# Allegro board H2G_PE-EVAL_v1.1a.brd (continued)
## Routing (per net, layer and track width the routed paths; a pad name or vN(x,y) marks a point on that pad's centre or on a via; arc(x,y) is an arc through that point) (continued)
N08455: length 2.8
  TOP w0.254: R11.2 85.78,77.09 85,77.86 U3.11
N08467: length 6
  TOP w0.254: R11.1 93.1,77.09 93.24,76.95 C20.2
N09759: length 33
  TOP w0.254: R14.2 67.06,74.82 68.19,75.95 72.14,75.95 v1(74.42,73.66) ; U3.7 80.92,77.36 v1(81.53,77.98)
  TOP w0.635: R14.2 65.53,74.42 63.43,76.52 63.43,78.67 63.88,79.12 Q3.3 Q3.1
  BOTTOM w0.254: v1(74.42,73.66) 80.01,73.66 81.53,75.18 v1(81.53,77.98)
N09873: length 35.9
  TOP w0.254: Q3.8 71.43,81.66 73.08,83.31 80.52,83.31 82.04,81.79 R12.2
  TOP w0.635: Q3.6 70.49,80.39 ; Q3.6 68.55,79.12 Q3.9 68.55,80.39 70.49,80.39 ; Q3.6 Q3.5 ; 70.49,80.39 Q3.8 70.49,87.73 69.56,88.66 TX1.4
N10901: length 17.3
  TOP w0.254: U3.6 79.06,77.86 78.74,77.54 v1(78.74,75.95) ; v1(73.91,75.95) 73.15,76.71 65.68,76.71 65.15,77.24 Q3.4
  BOTTOM w0.254: v1(78.74,75.95) v1(73.91,75.95)
N10913: length 5.2
  TOP w0.254: R12.1 88.15,81.03 87.9,80.77 85.34,80.77 84.94,80.36 U3.16
N10917: length 2.7
  TOP w0.254: R13.1 85.26,79.88 84.74,79.36 U3.14
N11491: length 3
  TOP w0.635: TX1.12 81.66,94.66 D7.2
N11495: length 2.8
  TOP w0.635: TX1.11 82.08,92.66 D6.2
N11499: length 2.7
  TOP w0.635: TX1.10 82.36,90.66 D5.2
N11507: length 2.6
  TOP w0.635: D8.2 65.78,84.66 TX1.6
N11532: length 2.5
  TOP w0.635: TX1.5 65.5,86.66 D9.2
N38522: length 2.4
  TOP w0.635: R15.2 D17.2
N38634: length 3.2
  TOP w0.635: R16.2 D18.2
N41110: length 4.8
  TOP w0.381: U6.6 84.3,15.37 84.59,15.67 C50.1
N41352: length 3.8
  TOP w0.381: U7.6 59.73,15.37 60.46,16.11 C51.1
N48243: length 24.5
  TOP w0.254: v1(14.99,67.56) 14.38,67.56 14.27,67.45 U16.3 ; C62.2 v1(24.47,79.63) 24.47,81.25 24.64,81.42 ; R35.2 24.64,81.42 24.64,81.42 ; 24.64,81.42 24.64,81.15 24.89,80.9 R37.2
  LAYER3 w0.254: v1(24.47,79.63) 20.55,75.71 17.54,75.71 16.11,74.28 16.11,68.69 v1(14.99,67.56)
N48256: length 3.1
  TOP w0.254: U20.7 28.92,80.9 27.65,82.17 R35.1
N48260: length 3.1
  TOP w0.254: R36.1 27.65,83.44 28.92,82.17 U20.6
N48264: length 31.1
  TOP w0.254: 13.96,82.19 14.1,82.19 C61.1 ; 13.96,82.19 11.43,79.66 11.43,68.58 11.91,68.1 U16.2 ; 13.96,82.19 13.96,83.36 ; R38.1 14.14,83.36 13.96,83.36 ; 13.96,83.36 15.17,84.58 24.68,84.58 25.39,83.87 R36.2
N48807: length 16.8
  TOP w0.254: 42.93,80.9 50.67,80.9 52.32,82.55 R33.2 ; 42.93,80.9 U20.2 ; 42.93,80.9 43.02,80.99 R39.1 43.04,82.44 C58.1
N51115: length 28.2
  TOP w0.254: R43.2 23.37,75.18 23.11,74.93 23.11,72.39 ; 23.11,72.39 23.11,72.39 23.11,71.42 ; 23.11,72.39 R41.2 ; U16.5 14.48,66.15 14.91,65.72 v1(14.91,64.85) ; 23.11,71.42 22.8,71.12 21.08,71.12 v1(20.32,71.88) ; 23.11,71.42 23.67,70.87 C67.2
  LAYER3 w0.254: v1(20.32,71.88) 19.3,70.87 19.3,66.04 18.11,64.85 v1(14.91,64.85)
N51119: length 2.4
  TOP w0.254: 29.43,72.52 28.17,72.52 28.04,72.39 R41.1
N51123: length 2.4
  TOP w0.254: R42.1 U21.6
N51127: length 41.1
  TOP w0.254: U16.6 10.7,65.5 10.17,66.03 v1(10.17,75.95) ; C66.1 R44.1 14.21,80.76 14.73,81.28 17.02,81.28 17.4,80.9 v1(17.4,74.27) ; R42.2 24.5,73.79 v1(24.14,74.14)
  LAYER3 w0.254: v1(24.14,74.14) 23.36,74.14 23.23,74.27 v1(17.4,74.27)
  BOTTOM w0.254: v1(17.4,74.27) 16.48,75.18 10.93,75.18 v1(10.17,75.95)
N51293: length 160.9
  TOP w0.254: R40.2 117.6,8.13 115.57,6.1 v1(115.57,2.29) ; C63.1 R45.1 45.97,73.91 46.99,72.9 v1(46.99,70.61) 42.42,70.61 41.66,71.37 41.66,72.29 41.43,72.52 40.17,72.52
  LAYER2 w0.254: v1(46.99,70.61) 46.99,51.31 47.75,50.55 47.75,39.62 49.02,38.35 v1(49.02,6.86)
  LAYER3 w0.254: v1(115.57,2.29) 115.06,1.78 98.3,1.78 96.27,3.81 93.47,3.81 91.44,1.78 50.04,1.78 49.02,2.79 v1(49.02,6.86)
N52251: length 12.7
  TOP w0.254: 26.16,64.01 26.21,64.06 26.21,66.37 25.91,66.68 R49.2 24.82,66.68 24.29,66.15 U16.10 ; 26.16,64.01 26.16,63.04 25.51,62.4 C72.2 ; 26.16,64.01 R47.2
N52255: length 2.4
  TOP w0.254: R47.1 U22.7
N52259: length 2.4
  TOP w0.254: U22.6 R48.1
N52263: length 24.5
  TOP w0.254: v1(12.95,73.15) 12.95,75.9 13.51,76.45 C71.1 R50.1 ; v1(16.51,65.79) 17.29,65.79 17.58,65.5 U16.9 24.59,65.5 24.82,65.28 R48.2
  BOTTOM w0.254: v1(16.51,65.79) 16.51,69.36 15.21,70.67 13.39,70.67 12.95,71.1 v1(12.95,73.15)
N52425: length 150.7
  TOP w0.254: R46.2 118.36,5.84 117.6,5.08 v1(117.6,2.03) ; C68.1 R51.1 45.57,65.28 46.06,64.79 v1(46.06,64.01) 46.06,62.57 45.72,62.23 42.42,62.23 41.66,62.99 41.66,63.78 41.43,64.01 U22.2
  LAYER2 w0.254: v1(47.75,37.08) v1(47.75,5.84)
  LAYER3 w0.254: v1(117.6,2.03) 116.92,1.35 49.45,1.35 47.75,3.05 v1(47.75,5.84)
  BOTTOM w0.254: v1(47.75,37.08) 47.75,38.1 46.74,39.12 46.74,63.33 v1(46.06,64.01)
N53429: length 26.6
  TOP w0.254: R53.2 C77.2 24.43,53.98 24.05,53.59 23.11,53.59 22.61,54.1 v1(22.61,60.96) 22.86,61.21 24.89,61.21 25.13,60.97 R55.2 ; v1(20.54,67.85) 20.14,67.45 U16.12
  BOTTOM w0.254: v1(22.61,60.96) 22.61,64.52 20.54,66.58 v1(20.54,67.85)
N53433: length 2.7
  TOP w0.254: U23.7 R53.1
N53437: length 2.7
  TOP w0.254: U23.6 R54.1
N53441: length 33.6
  TOP w0.254: v1(24.13,60.2) 24.13,57.33 24.43,57.02 R54.2 ; R56.1 C76.1 14.21,72.72 14.72,72.21 16.49,72.21 v1(17.05,71.66) 17.6,71.11 17.6,68.41 17.9,68.1 U16.13
  LAYER3 w0.254: v1(24.13,60.2) 24.68,60.75 24.68,69.79 21.33,73.15 18.54,73.15 v1(17.05,71.66)
N53579: length 140.8
  TOP w0.254: R52.2 v1(119.63,1.52) ; C73.1 R57.1 45.21,57.4 v1(45.72,56.9) ; U23.2 41.43,55.75 41.66,55.52 41.66,54.61 43.43,52.83 v1(45.21,52.83)
  LAYER2 w0.254: v1(46.74,4.57) 46.74,50.04 45.21,51.56 v1(45.21,52.83) 45.21,54.11 45.72,54.62 v1(45.72,56.9)
  LAYER3 w0.254: v1(46.74,4.57) 46.74,3.05 48.87,0.91 119.02,0.91 v1(119.63,1.52)
N54653: length 31.1
  TOP w0.254: C82.2 24.62,46.23 ; 24.62,46.23 v1(24.58,46.23) 23.11,46.23 21.34,48.01 21.34,51.31 22.1,52.07 24.62,52.07 25.39,51.31 R61.2 ; 24.62,46.23 24.63,46.23 R59.2 ; U17.3 v1(14.38,49.29)
  LAYER3 w0.254: v1(24.58,46.23) 14.98,46.23 13.83,47.38 13.83,48.74 v1(14.38,49.29)
N54657: length 2.5
  TOP w0.254: U24.7 R59.1
N54661: length 2.5
  TOP w0.254: U24.6 R60.1
N54665: length 33.2
  TOP w0.254: v1(15.49,50.8) 14.71,50.8 13.85,49.94 U17.2 11.46,49.94 11.18,50.23 11.18,58.55 13.46,60.83 C81.1 R62.1 ; R60.2 24.38,48.26 23.62,49.02 v1(23.62,51.31)
  LAYER3 w0.254: v1(15.49,50.8) 17.78,53.09 21.84,53.09 v1(23.62,51.31)
N54807: length 63.4
  TOP w0.254: v1(76.71,27.43) R58.2 ; v1(44.7,46.23) 44.36,46.58 R63.1 ; R63.1 44.45,48.55 44.45,47.5 43.94,46.99 U24.2 ; R63.1 44.21,48.79 C78.1
  LAYER2 w0.254: v1(45.21,26.42) 44.7,26.92 v1(44.7,46.23)
  LAYER3 w0.254: v1(45.21,26.42) 75.69,26.42 v1(76.71,27.43)
N56809: length 28.9
  TOP w0.254: U17.5 11.77,47.99 11.18,47.4 11.18,46.48 12.7,44.96 14.48,44.96 14.99,45.47 21.59,45.47 25.01,42.05 R67.2 24,40.26 23.62,39.88 23.62,36.5 24.31,35.81 C87.2 R65.2
N56813: length 2.9
  TOP w0.254: U25.7 R65.1
N56817: length 2.9
  TOP w0.254: 29.43,38.99 R66.1
N56821: length 35.3
  TOP w0.254: 19.6,46.26 19.31,45.97 15.75,45.97 14.38,47.34 U17.6 ; 19.6,46.26 21.81,46.26 25.86,42.21 25.86,39.49 25.36,38.99 R66.2 ; 19.6,46.26 20.57,47.23 20.57,51.82 14.97,57.42 C86.1 R68.1
N56959: length 24
  TOP w0.254: 44.48,37.85 44.7,37.85 49.78,32.77 v1(51.56,32.77) ; 44.48,37.85 R69.1 44.48,40.75 C83.1 ; 44.48,37.85 44.36,37.72 U25.2
  TOP w0.635: R64.2 53.09,27.18 v1(52.32,27.94)
  LAYER2 w0.254: v1(51.56,32.77) 51.56,28.7 v1(52.32,27.94)
N58569: length 31.9
  TOP w0.254: U17.10 16.52,47.99 v1(16.51,48.01) ; v1(19.3,27.69) 20.07,28.45 20.07,29.7 21.61,31.24 R70.2 R71.1 C88.1
  BOTTOM w0.254: v1(19.3,27.69) 18.29,27.69 17.27,28.7 17.27,40.64 15.93,41.99 15.93,47.42 v1(16.51,48.01)
N59411: length 47.3
  TOP w0.254: v1(33.57,49.29) 33.57,34.25 36.45,31.37 R72.2 R73.1 C89.1 ; U17.12 v1(16.51,49.29)
  LAYER3 w0.254: v1(16.51,49.29) v1(33.57,49.29)
N71004: length 23.1
  TOP w0.254: 15.24,30.73 15.55,31.04 U27.6 18.2,31.04 R75.2 ; 15.24,30.73 15.24,32.34 ; 15.24,30.73 15,30.49 C102.2 ; v1(13.71,31.25) 14.8,32.34 15.24,32.34 ; ADC1.7 11.62,39.79 11.45,39.62 v1(10.67,39.62) ; 15.24,32.34 U27.8
  BOTTOM w0.254: v1(13.71,31.25) 9.65,35.31 9.65,38.61 v1(10.67,39.62)
N126025: length 3.1
  TOP w0.254: R80.2 D19.2
N126027: length 2.9
  TOP w0.254: D25.2 R86.2
N126029: length 2.9
  TOP w0.254: D24.2 R85.2
N126031: length 2.9
  TOP w0.254: D23.2 R84.2
N126033: length 3.1
  TOP w0.254: R83.2 D22.2
N126035: length 2.9
  TOP w0.254: D26.2 R87.2
N126037: length 3.1
  TOP w0.254: R82.2 D21.2
N126039: length 3.1
  TOP w0.254: D20.2 R81.2
N179536: length 3.7
  TOP w0.635: U8.2 R17.2
N179562: length 5
  TOP w0.635: R88.1 113.38,100.97 U8.7 U8.6
N179712: length 4.2
  TOP w0.635: R19.2 123.21,101.09 123.34,100.97 U9.2
N179754: length 5.2
  TOP w0.635: R90.1 136.24,100.97 U9.7 U9.6
N179920: length 3.9
  TOP w0.635: U10.2 R21.2
N179946: length 5
  TOP w0.635: U10.6 U10.7 158.08,100.97 R92.1
N180096: length 4.1
  TOP w0.381: R23.2 75.95,62.04 76.77,62.87 U11.2
N180138: length 5.9
  TOP w0.635: U11.6 U11.7 89.53,62.87 R24.1
N180288: length 3.7
  TOP w0.635: R25.2 U12.2
N180330: length 5
  TOP w0.635: R89.1 113.38,82.93 U12.7 111.13,80.39
N180476: length 3.7
  TOP w0.635: R27.2 U13.2
N180502: length 5.2
  TOP w0.635: R91.1 136.24,82.93 U13.7 133.74,80.39
N180632: length 3.7
  TOP w0.635: R29.2 U14.2
N180674: length 5.2
  TOP w0.635: R93.1 158.34,82.93 U14.7 155.83,80.39
N180804: length 4.1
  TOP w0.381: U15.2 53.28,62.48 52.32,61.53 R31.2
N180846: length 6.3
  TOP w0.635: U15.6 U15.7 65.93,62.48 67.06,63.61 R32.1
N223775: length 3.1
  TOP w0.381: C105.1 54.74,52.31 54.88,52.45 U30.6
N248745: length 1.9
  TOP w0.254: U31.6 78.59,52.06 C108.1

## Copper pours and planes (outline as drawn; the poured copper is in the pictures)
GND on TOP: 127.25,73.66 127,73.91 127,76.71 127.25,76.96 131.06,76.96 131.32,76.71 131.32,73.91 131.06,73.66
GND on TOP: 55.37,24.89 54.86,24.38 54.86,22.1 55.12,21.84 57.15,21.84 57.4,22.1 57.4,24.38 56.9,24.89
GND on TOP: 112.78,75.95 112.78,76.96 113.28,77.47 122.17,77.47 123.7,75.95 134.87,75.95 136.4,77.47 142.24,77.47 143.76,75.95 157.23,75.95 158.75,77.47 161.8,77.47 162.31,76.96 162.31,75.95 161.8,75.44 158.5,75.44 156.72,73.66 141.22,73.66 139.45,75.44 136.4,75.44 134.62,73.66 118.62,73.66 116.84,75.44 113.28,75.44
GND on TOP: 78.74,24.89 78.23,24.38 78.23,22.1 78.49,21.84 80.52,21.84 80.77,22.1 80.77,24.38 80.26,24.89
GND on BOTTOM: 89.41,107.95 87.12,107.95 86.61,107.44 86.61,6.6 85.34,5.33 67.31,5.33 66.55,6.1 66.55,7.87 65.53,8.89 63.25,8.89 61.98,7.62 61.98,2.29 62.99,1.27 89.66,1.27 90.68,2.29 90.68,19.05 94.49,22.86 94.49,46.74 89.92,51.31 89.92,107.44
GND on BOTTOM: 87.12,104.14 89.66,104.14 90.17,104.65 90.17,110.24 90.93,111 142.75,111 144.02,109.73 144.02,108.2 144.53,107.7 146.3,107.7 147.07,108.46 147.07,109.73 148.34,111 151.13,111 151.64,111.51 151.64,113.03 151.13,113.54 88.39,113.54 86.61,111.76 86.61,104.65
GND on BOTTOM: 127.76,113.54 127,112.78 127,73.91 127.25,73.66 131.06,73.66 131.32,73.91 131.32,112.78 130.56,113.54
GND on BOTTOM: 91.44,25.4 94.23,25.4 94.74,24.89 94.74,20.83 93.47,19.56 55.88,19.56 54.86,20.57 54.86,24.38 55.37,24.89 56.9,24.89 57.4,24.38 57.4,23.37 58.67,22.1 66.55,22.1 67.06,22.61 67.06,24.64 67.82,25.4 69.85,25.4 70.61,24.64 70.61,22.61 71.12,22.1 77.22,22.1 78.23,23.11 78.23,24.38 78.74,24.89 80.26,24.89 80.77,24.38 80.77,23.37 82.04,22.1 89.66,22.1 90.93,23.37 90.93,24.89
GND on BOTTOM: 90.17,107.44 90.17,104.65 89.66,104.14 74.17,104.14 70.1,108.2 65.28,108.2 61.98,104.9 57.91,104.9 54.1,108.71 54.1,110.24 55.12,111.25 76.45,111.25 79.76,107.95 89.66,107.95
GND_SIGNAL on LAYER2: 0.76,88.65 7.37,88.65 7.37,97.28 26.91,97.28 26.94,91.46 34.29,91.42 34.29,27.18 42.42,27.18 42.42,0.76 0.76,0.76
DC-LINK on TOP: 94.49,54.61 94.49,55.88 93.98,56.39 68.07,56.39 67.56,55.88 67.56,54.61 68.07,54.1 73.91,54.1 74.42,54.61 90.68,54.61 90.93,54.36 94.23,54.36
DC-LINK on TOP: 162.05,92.46 161.29,93.22 113.79,93.22 112.78,92.2 112.78,91.19 113.79,90.17 161.04,90.17 162.05,91.19
DC-LINK on TOP: 130.56,90.17 127.76,90.17 127,90.93 127,112.78 127.76,113.54 130.56,113.54 131.32,112.78 131.32,90.93
DC-LINK on TOP: 82.8,111.25 82.8,113.03 83.31,113.54 154.18,113.54 154.69,113.03 154.69,111.51 154.18,111 144.53,111 143.26,109.73 143.26,108.2 142.75,107.7 141.22,107.7 140.72,108.2 140.72,109.98 139.7,111 97.54,111 96.01,109.47 96.01,104.65 95.5,104.14 91.69,104.14 91.19,104.65 91.19,109.47 89.92,110.74 83.31,110.74
DC-LINK on BOTTOM: 95.25,86.61 95.25,106.93 94.23,107.95 92.96,107.95 91.95,106.93 91.95,86.11 94.49,83.57 94.49,56.9 93.98,56.39 90.93,56.39 90.68,56.13 90.68,54.61 90.93,54.36 95.76,54.36 97.54,56.13 97.54,84.33
IGBT_S1 on TOP: 93.73,53.85 90.68,53.85 89.92,53.09 89.92,46.48 78.23,34.8 78.23,25.65 78.74,25.15 80.26,25.15 80.77,25.65 80.77,33.27 94.49,46.99 94.49,53.09
IGBT_S1 on TOP: 94.49,50.04 94.49,53.09 93.73,53.85 90.68,53.85 89.92,53.09 89.92,52.32 89.15,51.56 83.57,51.56 83.31,51.31 83.31,49.78 83.57,49.53 93.98,49.53
IGBT_S2 on TOP: 70.61,53.59 67.06,53.59 66.55,53.09 66.55,46.23 54.86,34.54 54.86,25.65 55.37,25.15 56.9,25.15 57.4,25.65 57.4,33.02 71.12,46.74 71.12,53.09
IGBT_S2 on TOP: 71.12,50.04 71.12,53.09 70.61,53.59 67.06,53.59 66.55,53.09 66.55,52.07 66.04,51.56 60.71,51.56 60.45,51.31 60.45,49.78 60.71,49.53 70.61,49.53
V_BUCK-1 on TOP: 83.31,32.26 83.31,26.67 90.17,19.81 90.17,14.99 89.66,14.48 87.63,14.48 87.38,14.22 87.38,12.7 87.63,12.45 91.19,12.45 92.2,13.46 92.2,22.61 86.61,28.19 86.61,32.26 86.11,32.77 83.82,32.77
V_BUCK-2 on TOP: 59.69,32.51 59.69,26.42 66.29,19.81 66.29,14.99 65.79,14.48 63.75,14.48 63.5,14.22 63.5,12.7 63.75,12.45 67.31,12.45 68.33,13.46 68.33,22.61 62.74,28.19 62.74,32.26 62.23,32.77 59.94,32.77
VA on TOP: 113.54,52.58 108.71,52.58 105.92,49.78 105.92,30.23 99.31,23.62 99.31,19.3 100.84,17.78 120.14,17.78 124.21,13.72 124.21,7.62 124.97,6.86 127.76,6.86 128.52,7.62 128.52,18.03 120.14,26.42 120.14,42.67 116.08,46.74 116.08,50.04
VB on TOP: 133.1,6.86 130.56,6.86 129.79,7.62 129.79,19.05 127,21.84 127,51.05 128.27,52.32 134.62,52.32 136.14,50.8 136.14,21.59 133.86,19.3 133.86,7.62
VC on TOP: 153.92,52.32 149.35,52.32 147.07,50.04 147.07,46.74 143.51,43.18 143.51,26.92 135.13,18.54 135.13,7.62 135.89,6.86 138.68,6.86 139.45,7.62 139.45,13.97 144.53,19.05 162.05,19.05 163.32,20.32 163.32,24.38 156.46,31.24 156.46,49.78
VMID1 on TOP: 115.82,74.93 114.05,74.93 112.78,73.66 112.78,71.12 109.22,67.56 109.22,63.25 109.98,62.48 116.59,62.48 117.35,63.25 117.35,73.41
VMID1 on BOTTOM: 113.54,93.73 113.54,95.25 114.05,95.76 118.36,95.76 119.89,94.23 119.89,73.41 118.62,72.14 114.05,72.14 113.54,72.64 113.54,74.42 114.05,74.93 116.59,74.93 117.35,75.69 117.35,92.46 116.59,93.22 114.05,93.22
VMID2 on TOP: 138.94,74.93 136.91,74.93 135.64,73.66 135.64,71.12 130.3,65.79 130.3,63.5 131.32,62.48 139.45,62.48 140.21,63.25 140.21,73.66
VMID2 on BOTTOM: 136.4,93.73 136.4,95.25 136.91,95.76 141.22,95.76 142.75,94.23 142.75,73.41 141.48,72.14 136.91,72.14 136.4,72.64 136.4,74.42 136.91,74.93 139.45,74.93 140.21,75.69 140.21,92.46 139.45,93.22 136.91,93.22
VMID3 on TOP: 161.04,74.93 159,74.93 157.73,73.66 157.73,71.88 151.13,65.28 151.13,63.25 151.89,62.48 161.54,62.48 162.31,63.25 162.31,73.66
VMID3 on BOTTOM: 158.5,93.73 158.5,95.25 159,95.76 163.32,95.76 164.34,94.74 164.34,72.9 163.58,72.14 159,72.14 158.5,72.64 158.5,74.42 159,74.93 161.29,74.93 162.05,75.69 162.05,92.46 161.29,93.22 159,93.22
N38702 on TOP: 89.66,17.02 89.41,17.27 86.87,17.27 84.58,14.99 84.58,10.16 81.53,7.11 81.53,6.1 82.3,5.33 83.31,5.33 86.36,8.38 86.36,13.97 87.38,14.99 89.41,14.99 89.66,15.24
N38762 on TOP: 65.79,17.02 65.53,17.27 62.74,17.27 60.71,15.24 60.71,10.67 57.4,7.37 57.4,6.35 58.17,5.59 59.44,5.59 62.48,8.64 62.48,13.97 63.5,14.99 65.53,14.99 65.79,15.24
N42617 on TOP: 63.75,96.77 63.75,106.68 65.28,108.2 67.56,108.2 69.09,106.68 69.09,102.36 70.36,101.09 78.99,101.09 79.76,100.33 79.76,98.81 78.99,98.04 69.85,98.04 68.07,96.27 64.26,96.27
N223929 on TOP: 62.74,54.1 59.18,54.1 57.66,52.58 57.66,46.74 59.69,44.7 62.48,44.7 62.99,45.21 62.99,47.24 61.98,48.26 60.96,48.26 59.94,49.28 59.94,51.56 60.45,52.07 62.74,52.07 62.99,52.32 62.99,53.85
N249090 on TOP: 85.6,54.1 82.04,54.1 80.52,52.58 80.52,46.74 82.55,44.7 85.34,44.7 85.85,45.21 85.85,47.24 84.84,48.26 83.82,48.26 82.8,49.28 82.8,51.56 83.31,52.07 85.6,52.07 85.85,52.32 85.85,53.85

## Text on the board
Ref Des/Silkscreen Top: User I/O | Buck Converter2 | + | 9V-36V | - | Buck Converter1 | H2G_PE-EVAL | V1.1A | Chris Farnell | 27Jun2019 | 3-Phase Converter | A | B | C
